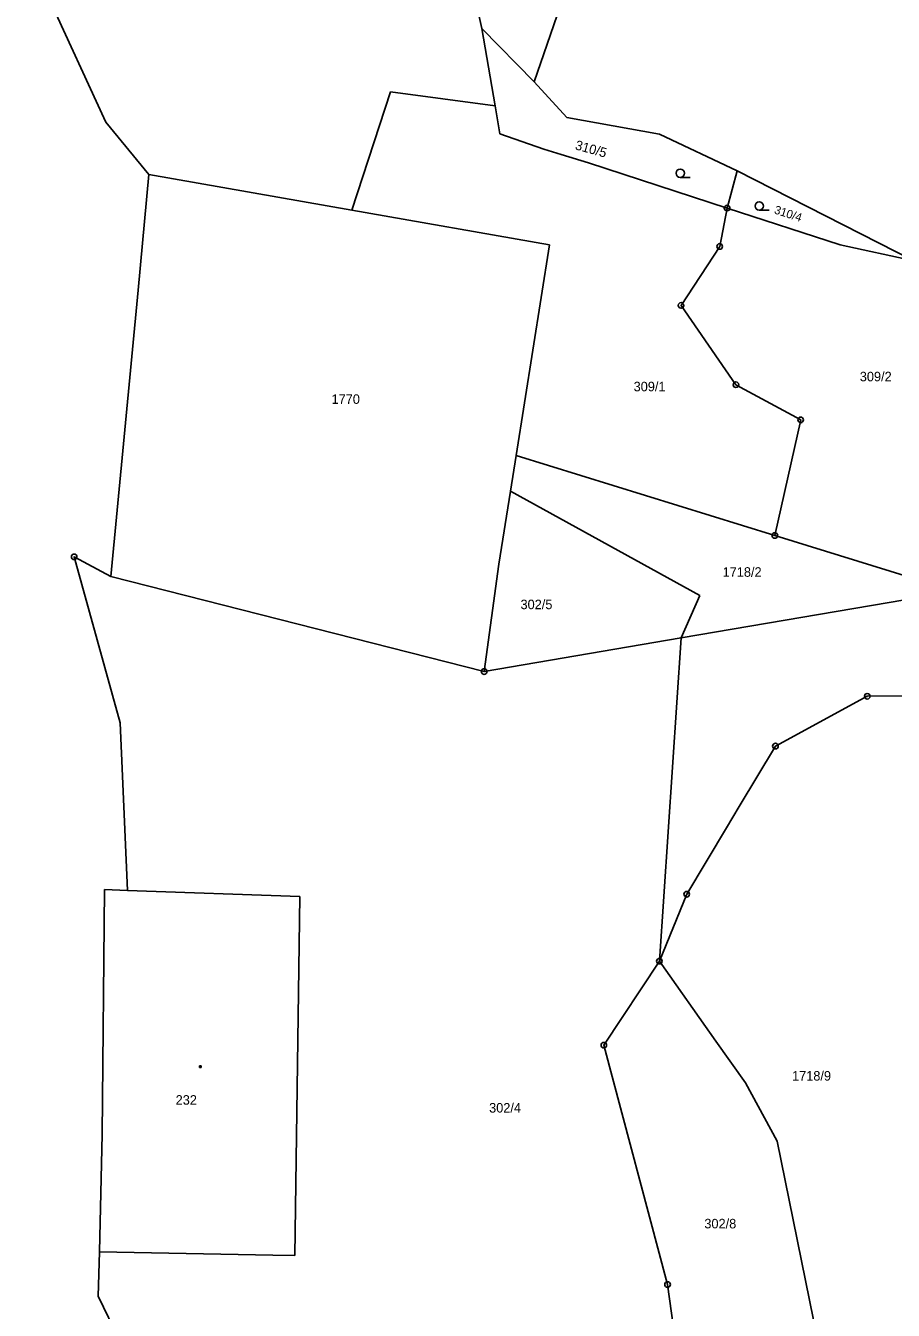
# Model space of a CAD drawing. Extents: x -717366 to -716792, y -1145485 to -1142762.
# Drawn here: x -717164.7 to -717087.3, y -1143043.5 to -1142929 of the extents above; entities that cross this region are included whole.
import ezdxf

# ---------------------------------------------------------------- set-up
doc = ezdxf.new("R2010")
doc.units = 0
doc.layers.add('Vrstva 1', color=7, linetype='Continuous')

msp = doc.modelspace()

# ---------------------------------------------------------------- linework, layer by layer
at = {"layer": 'Vrstva 1'}
for p, q in [((-717112.17, -1142913.19), (-717119.35, -1142933.96)), ((-717127.03, -1142915.45), (-717124, -1142929.21)), ((-717164.68, -1142921.99), (-717157.52, -1142937.57)), ((-717124, -1142929.21), (-717122.82, -1142936.12)), ((-717119.35, -1142933.96), (-717124, -1142929.21)), ((-717119.35, -1142933.96), (-717116.42, -1142937.14)), ((-717135.59, -1142945.42), (-717132.16, -1142934.85)), ((-717132.16, -1142934.85), (-717122.82, -1142936.12)), ((-717122.82, -1142936.12), (-717122.39, -1142938.62)), ((-717157.52, -1142937.57), (-717153.69, -1142942.24)), ((-717116.42, -1142937.14), (-717108.17, -1142938.64)), ((-717122.39, -1142938.62), (-717118.47, -1142939.97)), ((-717108.17, -1142938.64), (-717101.23, -1142941.91)), ((-717118.47, -1142939.97), (-717116.94, -1142940.44)), ((-717116.94, -1142940.44), (-717114.49, -1142941.19)), ((-717114.49, -1142941.19), (-717102.14, -1142945.23)), ((-717102.14, -1142945.23), (-717101.23, -1142941.91)), ((-717101.23, -1142941.91), (-717085.48, -1142949.94)), ((-717153.69, -1142942.24), (-717154.64, -1142952.54)), ((-717135.59, -1142945.42), (-717153.69, -1142942.24)), ((-717106.32, -1142942.5), (-717105.445, -1142942.5)), ((-717117.98, -1142948.51), (-717135.59, -1142945.42)), ((-717102.14, -1142945.23), (-717102.8, -1142948.65)), ((-717102.14, -1142945.23), (-717092.06, -1142948.52)), ((-717099.27, -1142945.42), (-717098.395, -1142945.42)), ((-717120.96, -1142967.3), (-717117.98, -1142948.51)), ((-717102.8, -1142948.65), (-717106.25, -1142953.91)), ((-717092.06, -1142948.52), (-717085.48, -1142949.94)), ((-717154.64, -1142952.54), (-717157.08, -1142978.08)), ((-717106.25, -1142953.91), (-717101.35, -1142960.98)), ((-717101.35, -1142960.98), (-717095.58, -1142964.12)), ((-717095.58, -1142964.12), (-717097.88, -1142974.43)), ((-717121.46, -1142970.48), (-717120.96, -1142967.3)), ((-717120.96, -1142967.3), (-717097.88, -1142974.43)), ((-717122.49, -1142976.98), (-717121.46, -1142970.48)), ((-717104.56, -1142979.79), (-717121.46, -1142970.48)), ((-717097.88, -1142974.43), (-717081.81, -1142979.4)), ((-717160.36, -1142976.33), (-717157.08, -1142978.08)), ((-717160.36, -1142976.33), (-717156.26, -1142991.13)), ((-717123.8, -1142986.56), (-717122.49, -1142976.98)), ((-717123.8, -1142986.56), (-717157.08, -1142978.08)), ((-717081.81, -1142979.4), (-717106.23, -1142983.56)), ((-717104.56, -1142979.79), (-717106.23, -1142983.56)), ((-717123.8, -1142986.56), (-717106.23, -1142983.56)), ((-717106.23, -1142983.56), (-717108.18, -1143012.39)), ((-717089.64, -1142988.77), (-717092.86, -1142990.52)), ((-717081.81, -1142988.69), (-717089.64, -1142988.77)), ((-717156.26, -1142991.13), (-717155.59, -1143006.08)), ((-717092.86, -1142990.52), (-717097.83, -1142993.21)), ((-717097.83, -1142993.21), (-717101.06, -1142998.6)), ((-717101.06, -1142998.6), (-717102.2, -1143000.5)), ((-717102.2, -1143000.5), (-717105.74, -1143006.42)), ((-717157.86, -1143027.83), (-717157.66, -1143006.01)), ((-717157.66, -1143006.01), (-717155.59, -1143006.08)), ((-717155.59, -1143006.08), (-717140.25, -1143006.61)), ((-717140.25, -1143006.61), (-717140.69, -1143038.65)), ((-717105.74, -1143006.42), (-717108.18, -1143012.39)), ((-717108.18, -1143012.39), (-717113.13, -1143019.88)), ((-717108.18, -1143012.39), (-717103.14, -1143019.51)), ((-717113.13, -1143019.88), (-717107.45, -1143041.23)), ((-717103.14, -1143019.51), (-717100.5, -1143023.25)), ((-717149.17, -1143021.73), (-717149.02, -1143021.73)), ((-717149.17, -1143021.88), (-717149.17, -1143021.73)), ((-717149.02, -1143021.88), (-717149.17, -1143021.88)), ((-717149.02, -1143021.73), (-717149.02, -1143021.88)), ((-717100.5, -1143023.25), (-717097.67, -1143028.45)), ((-717158.09, -1143038.32), (-717157.86, -1143027.83)), ((-717097.67, -1143028.45), (-717093.66, -1143048.26)), ((-717158.23, -1143042.26), (-717158.09, -1143038.32)), ((-717142.65, -1143038.61), (-717158.09, -1143038.32)), ((-717140.69, -1143038.65), (-717142.65, -1143038.61)), ((-717107.45, -1143041.23), (-717104.78, -1143060.84)), ((-717156.31, -1143046.17), (-717158.23, -1143042.26))]:
    msp.add_line(p, q, dxfattribs=at)
for centre, radius in [((-717106.32, -1142942.125), 0.375), ((-717102.14, -1142945.23), 0.25), ((-717102.14, -1142945.23), 0.005), ((-717099.27, -1142945.045), 0.375), ((-717102.8, -1142948.65), 0.25), ((-717102.8, -1142948.65), 0.005), ((-717106.25, -1142953.91), 0.25), ((-717106.25, -1142953.91), 0.005), ((-717101.35, -1142960.98), 0.25), ((-717101.35, -1142960.98), 0.005), ((-717095.58, -1142964.12), 0.25), ((-717095.58, -1142964.12), 0.005), ((-717097.88, -1142974.43), 0.25), ((-717097.88, -1142974.43), 0.005), ((-717160.36, -1142976.33), 0.25), ((-717160.36, -1142976.33), 0.005), ((-717123.8, -1142986.56), 0.25), ((-717123.8, -1142986.56), 0.005), ((-717089.64, -1142988.77), 0.25), ((-717089.64, -1142988.77), 0.005), ((-717097.83, -1142993.21), 0.25), ((-717097.83, -1142993.21), 0.005), ((-717105.74, -1143006.42), 0.25), ((-717105.74, -1143006.42), 0.005), ((-717108.18, -1143012.39), 0.25), ((-717108.18, -1143012.39), 0.005), ((-717113.13, -1143019.88), 0.25), ((-717113.13, -1143019.88), 0.005), ((-717107.45, -1143041.23), 0.25), ((-717107.45, -1143041.23), 0.005)]:
    msp.add_circle(centre, radius, dxfattribs=at)

# ---------------------------------------------------------------- texts
for s, height, rotation, p in [('310/5', 0.85, 344.49345, (-717115.75, -1142939.98)), ('310/4', 0.75, 342, (-717097.998, -1142945.692))]:
    msp.add_text(s, height=height, rotation=rotation, dxfattribs=at).set_placement(p)
for s, p in [('309/2', (-717090.309, -1142960.68)), ('309/1', (-717110.476, -1142961.57)), ('1770', (-717137.41, -1142962.69)), ('1718/2', (-717102.54, -1142978.11)), ('302/5', (-717120.56, -1142981)), ('1718/9', (-717096.35, -1143023.04)), ('232', (-717151.31, -1143025.19)), ('302/4', (-717123.36, -1143025.89)), ('302/8', (-717104.169, -1143036.22))]:
    msp.add_text(s, height=0.85, dxfattribs=at).set_placement(p)

doc.saveas('drawing.dxf')
